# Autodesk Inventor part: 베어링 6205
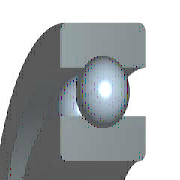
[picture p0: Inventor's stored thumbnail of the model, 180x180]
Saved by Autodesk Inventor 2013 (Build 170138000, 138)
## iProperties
Created: 2012-02
Part Number: 베어링 6205
Material: 강철, 연강
Description: 깊은 그루브 볼 베어링
Document SubType Name: Modeling
Standard: KS B 2023
Designer: mduedu
Standards Organization: KS
Language: ko-KR
Size Designation: 6205 - 25 x 52 x 15
Categories: <MemberInstance><Categories><Category DisplayName="샤프트 부품" InternalName="7f7aeb1f-a693-4053-b835-cee3144e0d98" Mnemonic="SHFT"><Category DisplayName="베어링" Inter
Density: 1 g/cm^3
IsCustomPart: 1
Author: mduedu
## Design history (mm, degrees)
sketch "스케치" dims "d0" = 7.02 (= -0.26 x WD + 0.26 x BD)
  geometry: L1 (3.99, 19.25)-(11.01, 19.25); L2 (7.5, 19.25)-(7.5, 15.74); L3 (7.5, 19.25)-(7.5, 22.76); L4 (4.892, 16.901)-(0, 16.901); L5 (0, 12.5)-(15, 12.5); L6 (4.892, 21.599)-(0, 21.599); L7 (0, 26)-(15, 26); L8 (15, 12.5)-(15, 16.901); L9 (10.108, 16.901)-(15, 16.901); L10 (10.108, 21.599)-(15, 21.599); L11 (15, 26)-(15, 21.599); L12 (-1.4, 0)-(8.4, 0) reference; L13 (0, -0.3)-(0, 5.3) reference
  constraints: 22 end point, 4 point on line, 2 collinear, 2 perpendicular, 2 symmetric about line, 1 midpoint, 1 parallel, 14 other
  dimensions: "d9" = 25 diameter of L5 L12 (= WD); "d11" = 52 diameter of L7 L12 (= BD); "d12" = 15 distance between parallel lines of L8 L13 (= KB); "d13" = 33.802 diameter of L9 L12 (= 0.326 x BD + 0.674 x WD)
revolve "본체" stored, may be unused: angle "d6" = 90 deg
revolve "볼" stored, may be unused: angle "d7" = 90 deg
pattern_circular "IDS_ARRAYBALL[SIMPL:T]" dims angle "d3" = 360 deg
body "Solid1"
fillet "모깎기1" dims "d1" = 1 (= KRS)
other parameters: "WD" = 25 [user parameter; used in 5 equation terms], "BD" = 52 [user parameter; used in 5 equation terms], "KB" = 15 [user parameter; used in 1 equation term], "KRS" = 1 [user parameter; used in 1 equation term], "d4" = 0, "d5" = 0, "d8" = 0, "d14" = 0, "d15" = 0, "BBA" = 0 [user parameter], "BC0" = 7800000 [user parameter], "BC" = 1.4e+07 [user parameter], "BR" = 26 (= 0.5 x BD) [user parameter], "WR" = 12.5 (= 0.5 x WD) [user parameter]
